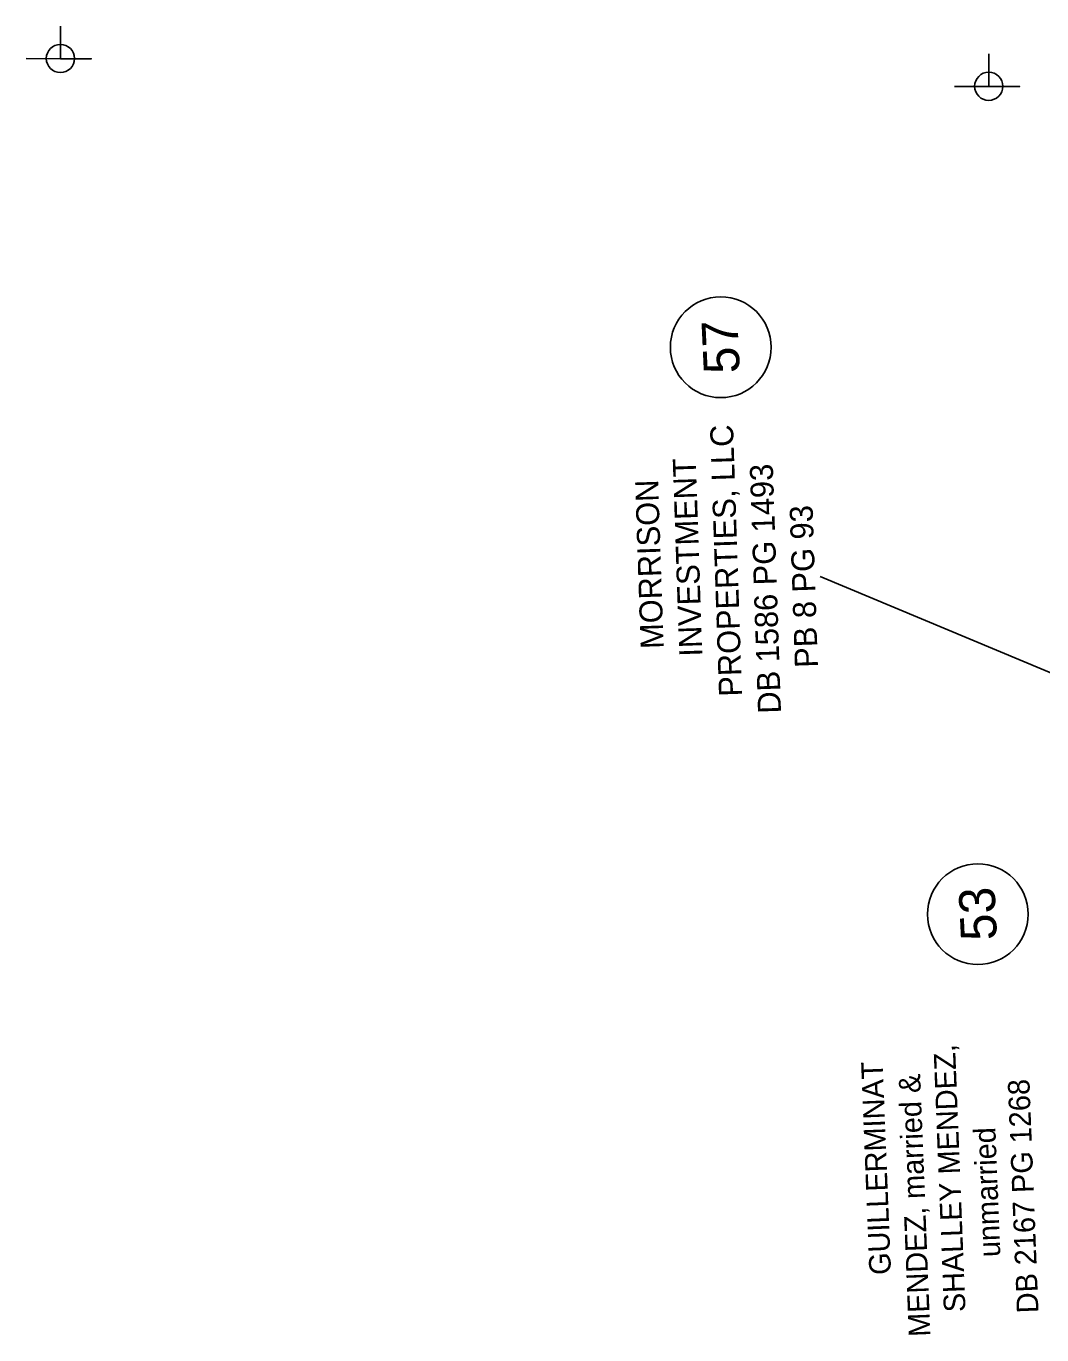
# Model space of a CAD drawing. Extents: x 1627482 to 1629573, y 760826 to 766301.
# Drawn here: x 1627926 to 1628102.4, y 764564.6 to 764791.9 of the extents above; entities that cross this region are included whole.
import ezdxf

# ---------------------------------------------------------------- set-up
doc = ezdxf.new("R2010")
doc.units = 0
for name, color, linetype in [('Exist Property Deed Book Text', 7, 'Continuous'), ('Exist Property Line Leader', 7, 'Continuous'), ('Exist Property Owner Number CELL', 7, 'Continuous'), ('Exist Property Owner Text', 7, 'Continuous'), ('Exist Utilities Power Joint Use Telephone CELL', 7, 'Continuous')]:
    doc.layers.add(name, color=color, linetype=linetype)

msp = doc.modelspace()

# ---------------------------------------------------------------- linework, layer by layer
at = {"layer": 'Exist Property Line Leader'}
msp.add_line((1628269.12, 764610.41), (1628063.92, 764696.29), dxfattribs=at)
at = {"layer": 'Exist Property Owner Number CELL'}
for centre in [(1628046.63, 764736.09), (1628091.28, 764637.62)]:
    msp.add_circle(centre, 8.75, dxfattribs=at)
at = {"layer": 'Exist Utilities Power Joint Use Telephone CELL'}
for p, q in [((1627931.96, 764786.24), (1627931.96, 764786.24)), ((1628093.17, 764781.41), (1628093.17, 764781.41))]:
    msp.add_line(p, q, dxfattribs=at)
for points in [[(1627926.02, 764786.24), (1627937.36, 764786.2), (1627931.96, 764786.22), (1627931.96, 764791.87)], [(1628087.24, 764781.41), (1628098.57, 764781.37), (1628093.17, 764781.39), (1628093.17, 764787.04)]]:
    msp.add_lwpolyline(points, dxfattribs=at)
for centre in [(1627931.96, 764786.25), (1628093.17, 764781.42)]:
    msp.add_circle(centre, 2.45, dxfattribs=at)

# ---------------------------------------------------------------- texts
at = {"layer": 'Exist Property Deed Book Text'}
for s, height, rotation, p in [('DB 1586 PG 1493', 4, 91.909, (1628057.11, 764672.52)), ('PB 8 PG 93', 4, 91.909, (1628063.52, 764680.49)), ('DB 2167 PG 1268', 3.75, 92.2582, (1628101.82, 764568.38))]:
    msp.add_text(s, height=height, rotation=rotation, dxfattribs=at).set_placement(p)
at = {"layer": 'Exist Property Owner Number CELL'}
for s, p in [('57', (1628049.96, 764731.67)), ('53', (1628094.61, 764633.19))]:
    msp.add_text(s, height=6.25, rotation=92.6915, dxfattribs=at).set_placement(p)
at = {"layer": 'Exist Property Owner Text'}
for s, height, rotation, p in [('PROPERTIES, LLC', 4, 91.909, (1628050.34, 764675.48)), ('INVESTMENT', 4, 91.909, (1628043.44, 764682.42)), ('MORRISON', 4, 91.909, (1628036.73, 764683.76)), ('SHALLEY MENDEZ,', 3.75, 92.2582, (1628089.15, 764568.56)), ('GUILLERMINAT', 3.75, 92.2582, (1628076.21, 764575.04)), ('MENDEZ, married &', 3.75, 92.2582, (1628083.05, 764564.29)), ('unmarried', 3.75, 92.2582, (1628095.2, 764578.12))]:
    msp.add_text(s, height=height, rotation=rotation, dxfattribs=at).set_placement(p)

doc.saveas('drawing.dxf')
